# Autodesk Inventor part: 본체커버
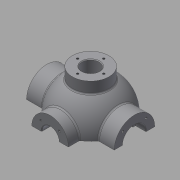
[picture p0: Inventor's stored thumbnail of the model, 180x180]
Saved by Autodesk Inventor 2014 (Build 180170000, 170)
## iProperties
Created: 2015-12
Part Number: 본체커버
Material: 알루미늄 6061
Document SubType Name: Modeling
Designer: mduedu
Density: 1 g/cm^3
Mass: 211.839 g
Surface Area: 451.737 cm^2
Volume: 211.839 cm^3
Appearance: 알루미늄 - 평지
Author: mduedu
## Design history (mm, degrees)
sketch "스케치1"
  geometry: L1 (-53, 0)-(53, 0); A1 r 53 centre (0, 0) between (53, 0) and (-53, 0); 2 further points
  constraints: 2 coincident, 2 end point, 2 point on circle, 1 centre point, 1 horizontal, 1 midpoint
  dimensions: "d0" = 53 radius of A1
revolve "회전1" sketch "스케치1" stored, may be unused: angle "d2" = 90 deg
feature "쉘1" dims "d11" = 10
node "작업 평면1"
sketch "스케치2"
  geometry: C1 r 31 at (0, 0); 1 further point
  constraints: 1 centre point, 1 coincident
  dimensions: "d4" = 62 diameter of C1
extrude "돌출1" join sketch "스케치2" stored distance "d5" = 10; taper "d6" = 0 deg
node "작업 평면2"
sketch "스케치3"
  geometry: C1 r 28 at (0, 0); 1 further point
  constraints: 1 centre point, 1 coincident
  dimensions: "d8" = 56 diameter of C1
extrude "돌출2" join sketch "스케치3" stored distance "d9" = 10; taper "d10" = 0 deg
hole "구멍1" diameter "d14" = 35; stored, may be unused: countersink angle "d18" = 90 deg, drill point angle "d20" = 0 deg; dims "d12" = 10, "d13" = 10, "d15" = 6, "d16" = 4, "d17" = 2, "d19" = 16
hole "구멍2" diameter "d23" = 27; stored, may be unused: countersink angle "d27" = 90 deg, drill point angle "d29" = 0 deg; dims "d21" = 10, "d22" = 10, "d24" = 6, "d25" = 4, "d26" = 2, "d28" = 16
fillet "모깎기1" dims "d30" = 0.3
hole "구멍3" diameter "d33" = 26; stored, may be unused: countersink angle "d37" = 90 deg, drill point angle "d39" = 0 deg; dims "d31" = 10, "d32" = 10, "d34" = 6, "d35" = 4, "d36" = 2, "d38" = 16
chamfer "모따기1" distance "d40" = 1; stored, may be unused: second distance "d41" = 2, angle "d42" = 45 deg
sketch "스케치4"
  geometry: L1 (0, 0)-(0, -25); L2 (0, 0)-(-17.678, -17.678); A1 r 25 centre (0, 0) between (-17.678, -17.678) and (0, -25); 1 further point
  constraints: 4 end point, 2 point on circle, 1 centre point, 1 coincident, 1 vertical
  dimensions: "d43" = 50 diameter of A1; "d47" = 45 deg angle of L1 L2
hole "구멍4" sketch "스케치4" at (-17.678, -17.678) diameter "d49" = 3.242; stored, may be unused: countersink angle "d53" = 90 deg, drill point angle "d55" = 118 deg; dims "d50" = 11, "d51" = 4, "d52" = 2, "d54" = 13
sketch "스케치5"
  geometry: L1 (0, 0)-(0, -20); L2 (0, 0)-(-14.142, -14.142); A1 r 20 centre (0, 0) between (0, -20) and (-14.142, -14.142); 2 further points
  constraints: 4 end point, 2 coincident, 2 point on circle, 1 centre point, 1 vertical
  dimensions: "d59" = 40 diameter of A1; "d65" = 45 deg angle of L1 L2
hole "구멍5" sketch "스케치5" at (-14.142, -14.142) diameter "d67" = 3.242; stored, may be unused: countersink angle "d71" = 90 deg, drill point angle "d73" = 118 deg; dims "d68" = 8, "d69" = 4, "d70" = 2, "d72" = 10
node "작업 평면3"
sketch "스케치6"
  geometry: C1 r 65 at (0, 0); 1 further point
  constraints: 1 centre point, 1 coincident
  dimensions: "d78" = 130 diameter of C1
extrude "돌출3" join sketch "스케치6" distance "d80" = 10; taper "d81" = 0 deg
sketch "스케치7"
  geometry: C1 r 20 at (0, 0); 1 further point
  constraints: 1 centre point, 1 coincident
  dimensions: "d82" = 40 diameter of C1
extrude "돌출4" join sketch "스케치7" stored distance "d84" = 10; taper "d85" = 0 deg
sketch "스케치8"
  geometry: 2 further points
  constraints: 1 coincident
hole "구멍6" sketch "스케치8" at (0, 0) diameter "d86" = 20; stored, may be unused: countersink angle "d90" = 90 deg, drill point angle "d92" = 118 deg; dims "d87" = 7, "d88" = 40, "d89" = 5, "d91" = 10
fillet "모깎기2" dims "d93" = 0.3
sketch "스케치9"
  geometry: L1 (65, -75)-(-65, -75) reference; L2 (-45, -75)-(-38.245, -36.692); A1 r 53 centre (0, 0) between (42.988, 31) and (42.988, -31) reference; 1 further point
  constraints: 2 end point, 1 point on circle, 1 point on line
  dimensions: "d94" = 45 horizontal distance of L2.start point (0, 0); "d95" = 80 deg angle of L2 L1
feature "리브1" sketch "스케치9" dims "d96" = 1, "d97" = 8, "d98" = 0, "d99" = 0, "d100" = 1, "d101" = 1
sketch "스케치10"
  geometry: L1 (0, 0)-(0, -55); L2 (0, 0)-(-38.891, -38.891); A1 r 55 centre (0, 0) between (0, -55) and (-38.891, -38.891); 2 further points
  constraints: 4 end point, 2 coincident, 2 point on circle, 1 centre point, 1 vertical
  dimensions: "d105" = 110 diameter of A1; "d107" = 45 deg angle of L1 L2
hole "구멍7" sketch "스케치10" at (-38.891, -38.891) diameter "d109" = 10; stored, may be unused: countersink angle "d113" = 90 deg, drill point angle "d115" = 118 deg; dims "d110" = 7, "d111" = 40, "d112" = 5, "d114" = 10
fillet "모깎기3" dims "d120" = 3
fillet "모깎기4" dims "d121" = 3, "d122" = 3
fillet "모깎기5" dims "d123" = 3
fillet "모깎기6" dims "d124" = 3
sketch "스케치11"
  geometry: C1 r 5 at (-38.891, 38.891) reference; C2 r 5 at (38.891, 38.891) reference; C3 r 5 at (38.891, -38.891) reference; C4 r 5 at (-38.891, -38.891) reference; C5 r 20 at (0, 0) reference; C6 r 65 at (0, 0) reference; 1 further point
  constraints: 3 other
feature "엠보싱1" sketch "스케치11" dims "d125" = 0.5, "d126" = 0
sketch "스케치12"
  geometry: L1 (0, 100)-(0, -100); L2 (0, 100)-(-150, 100); L3 (-150, 100)-(-150, -100); L4 (-150, -100)-(0, -100); 2 further points
  constraints: 8 end point, 3 perpendicular, 1 coincident, 1 midpoint, 1 vertical
  dimensions: "d127" = 200 distance of L2.end L3.end; "d129" = 150 distance of L3.end L1.end
extrude "돌출5" cut sketch "스케치12" stored distance "d130" = 10; taper "d131" = 0 deg
sketch "스케치13"
  geometry: C1 r 7 at (0, -53); A1 r 53 centre (0, 0) between (-42.113, -32.179) and (42.113, -32.179) reference; 1 further point
  constraints: 1 centre point, 1 point on circle
  dimensions: "d132" = 14 diameter of C1
extrude "돌출6" join sketch "스케치13" distance "d133" = 5; taper "d134" = 0 deg
sketch "스케치14"
  geometry: C1 r 7 at (0, 0) reference; 1 further point
extrude "돌출7" cut sketch "스케치14" stored distance "d135" = 5; taper "d136" = 0 deg
sketch "스케치15"
  geometry: C1 r 2.25 at (0, 53); A1 r 7 centre (0, 53) between (6.965, 52.302) and (-6.965, 52.302) reference; 1 further point
  constraints: 1 centre point, 1 coincident
  dimensions: "d139" = 4.5 diameter of C1
extrude "돌출8" cut sketch "스케치15" stored distance "d141" = 5; taper "d142" = 0 deg
fillet "모깎기7" dims "d143" = 3
fillet "모깎기8" dims "d144" = 1
fillet "모깎기9" dims "d145" = 1
fillet "모깎기10" dims "d146" = 1
node "작업 평면4"
sketch "스케치16"
  geometry: C1 r 28 at (0, 0); 1 further point
  constraints: 1 centre point, 1 coincident
  dimensions: "d148" = 56 diameter of C1
extrude "돌출9" join sketch "스케치16" stored distance "d150" = 5; taper "d151" = 0 deg
hole "구멍8" diameter "d154" = 26; stored, may be unused: countersink angle "d158" = 90 deg, drill point angle "d160" = 118 deg; dims "d152" = 10, "d153" = 10, "d155" = 6, "d156" = 4, "d157" = 2, "d159" = 8
sketch "스케치17" dims "d161" = 40
  geometry: 3 further points
  constraints: 2 vertical alignment, 1 coincident, 2 other
hole "구멍9" sketch "스케치17" at (0, 20) diameter "d163" = 3.242; stored, may be unused: countersink angle "d167" = 90 deg, drill point angle "d169" = 118 deg; dims "d164" = 8, "d165" = 4, "d166" = 2, "d168" = 10
fillet "모깎기11" dims "d173" = 3
chamfer "모따기2" distance "d174" = 1; stored, may be unused: second distance "d175" = 2, angle "d176" = 45 deg
node "솔리드1"
mirror "대칭1"
mirror "대칭2"
pattern_circular "원형 패턴1" dims angle "d57" = 360 deg
mirror "대칭3"
pattern_circular "원형 패턴2" dims angle "d75" = 360 deg
pattern_circular "원형 패턴3" dims angle "d103" = 360 deg
pattern_circular "원형 패턴4" dims angle "d118" = 360 deg
pattern_circular "원형 패턴5" dims angle "d171" = 360 deg
node "투영된 루프1"
other parameters: "d3" = 67, "d7" = 62, "d77" = -85, "d147" = 62
